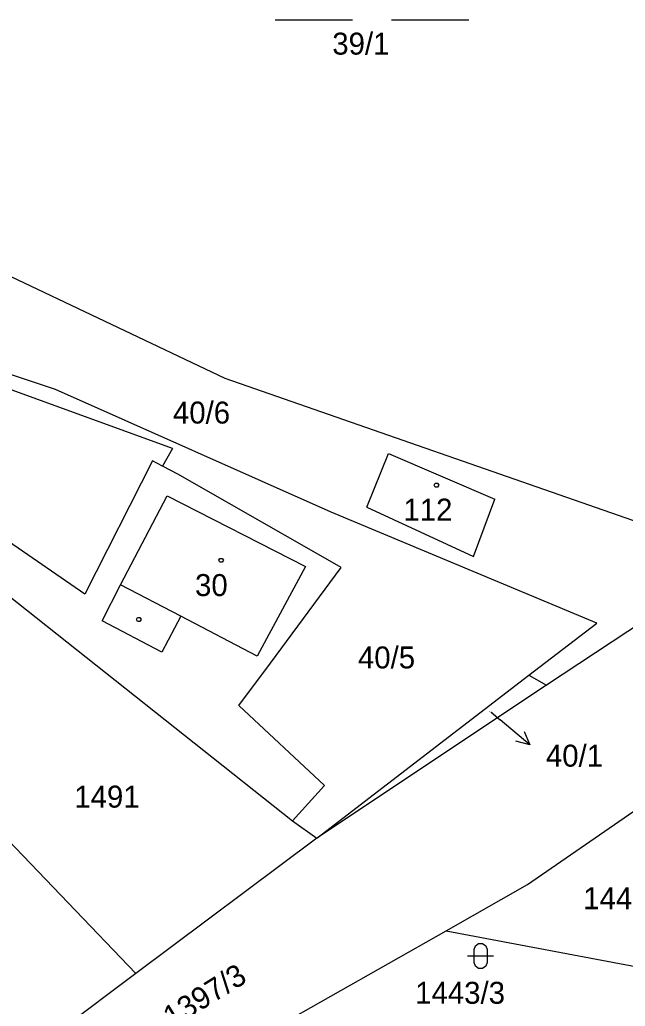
# Model space of a CAD drawing. Extents: x -852001 to -842497, y -1063614 to -1052182.
# Drawn here: x -849333.8 to -849286.9, y -1056255.4 to -1056179.1 of the extents above; entities that cross this region are included whole.
import ezdxf

# ---------------------------------------------------------------- set-up
doc = ezdxf.new("R2010")
doc.units = 0
for name, color, linetype in [('Default', 7, 'Continuous'), ('KN_HRANICE', 7, 'Continuous'), ('KN_KULTURY', 7, 'Continuous'), ('KN_PARCELY', 7, 'Continuous'), ('KN_SLUCKY', 7, 'Continuous')]:
    doc.layers.add(name, color=color, linetype=linetype)

# ---------------------------------------------------------------- blocks, each defined once
blk = doc.blocks.new('316')
at = {"layer": 'Default'}
for points in [[(-0.5, 1.5), (-0.4, 1.79), (-0.15, 1.97), (0.16, 1.97), (0.41, 1.79), (0.51, 1.5), (0.51, 0.5), (0.41, 0.21), (0.16, 0.03), (-0.15, 0.03), (-0.4, 0.21), (-0.5, 0.5), (-0.5, 1.5)], [(-1, 1), (0.27, 1), (1, 1)]]:
    blk.add_lwpolyline(points, dxfattribs=at)
blk = doc.blocks.new('803')
at = {"layer": 'Default'}
for p, q in [((-7.5, 0), (-1.5, 0)), ((1.5, 0), (7.5, 0))]:
    blk.add_line(p, q, dxfattribs=at)
blk = doc.blocks.new('10292')
at = {"layer": 'Default'}
blk.add_line((0, 3), (0, 0), dxfattribs=at)
blk.add_lwpolyline([(-0.5, 2), (0, 3), (0.5, 2)], dxfattribs=at)
blk = doc.blocks.new('402')
at = {"layer": 'Default'}
blk.add_lwpolyline([(0.09, 0.15), (0.18, 0), (0.09, -0.15), (-0.09, -0.15), (-0.18, 0), (-0.09, 0.15), (0.09, 0.15)], dxfattribs=at)

msp = doc.modelspace()

# ---------------------------------------------------------------- linework, layer by layer
at = {"layer": 'KN_HRANICE'}
for p, q in [((-849351.28, -1056190.95), (-849317.91, -1056206.78)), ((-849351.28, -1056190.95), (-849317.91, -1056206.78)), ((-849321.95, -1056212.23), (-849351.88, -1056201.36)), ((-849321.95, -1056212.23), (-849351.88, -1056201.36)), ((-849331, -1056207.66), (-849349.3, -1056201.62)), ((-849331, -1056207.66), (-849349.3, -1056201.62)), ((-849317.91, -1056206.78), (-849279.38, -1056220.21)), ((-849317.91, -1056206.78), (-849279.38, -1056220.21)), ((-849309.67, -1056217.15), (-849331, -1056207.66)), ((-849309.67, -1056217.15), (-849331, -1056207.66)), ((-849321.95, -1056212.23), (-849322.72, -1056213.6)), ((-849321.95, -1056212.23), (-849322.72, -1056213.6)), ((-849306.91, -1056216.78), (-849305.24, -1056212.62)), ((-849306.91, -1056216.78), (-849305.24, -1056212.62)), ((-849305.24, -1056212.62), (-849297, -1056216.16)), ((-849305.24, -1056212.62), (-849297, -1056216.16)), ((-849323.51, -1056213.18), (-849328.75, -1056223.5)), ((-849323.51, -1056213.18), (-849328.75, -1056223.5)), ((-849322.72, -1056213.6), (-849323.51, -1056213.18)), ((-849322.72, -1056213.6), (-849323.51, -1056213.18)), ((-849321.49, -1056214.25), (-849322.72, -1056213.6)), ((-849321.49, -1056214.25), (-849322.72, -1056213.6)), ((-849308.91, -1056221.45), (-849321.49, -1056214.25)), ((-849308.91, -1056221.45), (-849321.49, -1056214.25)), ((-849306.91, -1056216.78), (-849298.66, -1056220.6)), ((-849306.91, -1056216.78), (-849298.66, -1056220.6)), ((-849298.66, -1056220.6), (-849297, -1056216.16)), ((-849298.66, -1056220.6), (-849297, -1056216.16)), ((-849289.11, -1056225.75), (-849309.67, -1056217.15)), ((-849289.11, -1056225.75), (-849309.67, -1056217.15)), ((-849328.75, -1056223.5), (-849334.65, -1056219.42)), ((-849328.75, -1056223.5), (-849334.65, -1056219.42)), ((-849314.38, -1056228.83), (-849308.91, -1056221.45)), ((-849314.38, -1056228.83), (-849308.91, -1056221.45)), ((-849335.86, -1056222.66), (-849312.67, -1056241.03)), ((-849335.86, -1056222.66), (-849312.67, -1056241.03)), ((-849294.36, -1056229.78), (-849289.11, -1056225.75)), ((-849294.36, -1056229.78), (-849289.11, -1056225.75)), ((-849285.42, -1056225.55), (-849293.01, -1056230.55)), ((-849285.42, -1056225.55), (-849293.01, -1056230.55)), ((-849316.81, -1056232.12), (-849314.38, -1056228.83)), ((-849316.81, -1056232.12), (-849314.38, -1056228.83)), ((-849310.77, -1056242.39), (-849294.36, -1056229.78)), ((-849310.77, -1056242.39), (-849294.36, -1056229.78)), ((-849294.36, -1056229.78), (-849293.01, -1056230.55)), ((-849294.36, -1056229.78), (-849293.01, -1056230.55)), ((-849293.01, -1056230.55), (-849310.77, -1056242.39)), ((-849293.01, -1056230.55), (-849310.77, -1056242.39)), ((-849316.81, -1056232.12), (-849310.19, -1056238.3)), ((-849316.81, -1056232.12), (-849310.19, -1056238.3)), ((-849310.19, -1056238.3), (-849312.67, -1056241.03)), ((-849310.19, -1056238.3), (-849312.67, -1056241.03)), ((-849294.48, -1056245.96), (-849284.94, -1056239.39)), ((-849294.48, -1056245.96), (-849284.94, -1056239.39)), ((-849312.67, -1056241.03), (-849310.77, -1056242.39)), ((-849312.67, -1056241.03), (-849310.77, -1056242.39)), ((-849335.27, -1056241.92), (-849324.78, -1056252.85)), ((-849335.27, -1056241.92), (-849324.78, -1056252.85)), ((-849310.77, -1056242.39), (-849324.78, -1056252.85)), ((-849310.77, -1056242.39), (-849324.78, -1056252.85)), ((-849300.76, -1056249.55), (-849294.48, -1056245.96)), ((-849300.76, -1056249.55), (-849294.48, -1056245.96)), ((-849321.82, -1056261.46), (-849300.76, -1056249.55)), ((-849321.82, -1056261.46), (-849300.76, -1056249.55)), ((-849300.76, -1056249.55), (-849281.15, -1056253.26)), ((-849300.76, -1056249.55), (-849281.15, -1056253.26)), ((-849324.78, -1056252.85), (-849332.91, -1056258.92)), ((-849324.78, -1056252.85), (-849332.91, -1056258.92))]:
    msp.add_line(p, q, dxfattribs=at)
at = {"layer": 'KN_PARCELY'}
msp.add_line((-849297.28, -1056232.64), (-849296.59, -1056233.22), dxfattribs=at)
msp.add_line((-849297.28, -1056232.64), (-849296.59, -1056233.22), dxfattribs=at)
at = {"layer": 'KN_SLUCKY'}
for p, q in [((-849325.97, -1056222.79), (-849322.37, -1056215.9)), ((-849325.97, -1056222.79), (-849322.37, -1056215.9)), ((-849322.37, -1056215.9), (-849311.67, -1056221.36)), ((-849322.37, -1056215.9), (-849311.67, -1056221.36)), ((-849311.67, -1056221.36), (-849315.41, -1056228.3)), ((-849311.67, -1056221.36), (-849315.41, -1056228.3)), ((-849327.41, -1056225.56), (-849325.97, -1056222.79)), ((-849327.41, -1056225.56), (-849325.97, -1056222.79)), ((-849321.32, -1056225.2), (-849325.97, -1056222.79)), ((-849321.32, -1056225.2), (-849325.97, -1056222.79)), ((-849321.32, -1056225.2), (-849322.77, -1056227.98)), ((-849321.32, -1056225.2), (-849322.77, -1056227.98)), ((-849315.41, -1056228.3), (-849321.32, -1056225.2)), ((-849315.41, -1056228.3), (-849321.32, -1056225.2)), ((-849322.77, -1056227.98), (-849327.41, -1056225.56)), ((-849322.77, -1056227.98), (-849327.41, -1056225.56))]:
    msp.add_line(p, q, dxfattribs=at)

# ---------------------------------------------------------------- block references
at = {"layer": 'KN_KULTURY'}
for name, p in [('803', (-849306.51, -1056179.05)), ('803', (-849306.51, -1056179.05)), ('402', (-849301.52, -1056215.06)), ('402', (-849301.52, -1056215.06)), ('402', (-849318.19, -1056220.88)), ('402', (-849318.19, -1056220.88)), ('402', (-849324.57, -1056225.46)), ('402', (-849324.57, -1056225.46)), ('316', (-849298.11, -1056252.5)), ('316', (-849298.11, -1056252.5))]:
    msp.add_blockref(name, p, dxfattribs=at)
at = {"layer": 'KN_PARCELY', "rotation": -130.01474100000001}
msp.add_blockref('10292', (-849296.59, -1056233.22), dxfattribs=at)
msp.add_blockref('10292', (-849296.59, -1056233.22), dxfattribs=at)

# ---------------------------------------------------------------- texts
at = {"layer": 'KN_PARCELY'}
for s, height, p in [('39/1', 1.7, (-849309.586, -1056181.75)), ('39/1', 1.7, (-849309.586, -1056181.75)), ('40/6', 1.7, (-849321.919, -1056210.3)), ('40/6', 1.7, (-849321.919, -1056210.3)), ('112', 1.7, (-849304.08, -1056217.81)), ('112', 1.7, (-849304.08, -1056217.81)), ('30', 1.7, (-849320.209, -1056223.65)), ('30', 1.7, (-849320.209, -1056223.65)), ('40/5', 1.7, (-849307.599, -1056229.25)), ('40/5', 1.7, (-849307.599, -1056229.25)), ('40/1', 0.1, (-849297.461, -1056232.64)), ('40/1', 0.1, (-849297.461, -1056232.64)), ('40/1', 1.7, (-849293.05, -1056236.85)), ('40/1', 1.7, (-849293.05, -1056236.85)), ('1491', 1.7, (-849329.557, -1056240.02)), ('1491', 1.7, (-849329.557, -1056240.02)), ('1443/5', 1.7, (-849290.16, -1056247.88)), ('1443/5', 1.7, (-849290.16, -1056247.88)), ('1443/3', 1.7, (-849303.17, -1056255.2)), ('1443/3', 1.7, (-849303.17, -1056255.2))]:
    msp.add_text(s, height=height, dxfattribs=at).set_placement(p)
msp.add_text('1397/3', height=1.7, rotation=31.742, dxfattribs=at).set_placement((-849321.993, -1056257.112))
msp.add_text('1397/3', height=1.7, rotation=31.742, dxfattribs=at).set_placement((-849321.993, -1056257.112))

doc.saveas('drawing.dxf')
